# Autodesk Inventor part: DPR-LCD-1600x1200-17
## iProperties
Created: 2004-11
Part Number: DPR-LCD-1600x1200-17
Cost Center: 0 lbmass
Document SubType Name: Modeling
Designer: busseym
Manufacturer: Standard
Standards Organization: Custom
Description: LCD MONITOR, 1600X1200
Stock Number: DPR-LCD-1600x1200-17
Density: 1 g/cm^3
Dept. ID: Product Design
Description #2: ---
Finish #1: ---
Finish #2: ---
Material ID: ---
Project Number: ---
Author: busseym
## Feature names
1. Extrusion1
2. Extrusion2
3. Extrusion3
4. Revolution1
5. Extrusion4
6. Hole1
7. Rectangular Pattern1
8. Extrusion5
9. Extrusion6
10. Extrusion7
11. Extrusion8
12. Extrusion9
13. Extrusion10
14. Extrusion11
15. Hole3
16. Extrusion12
17. Hole4
18. USB BPort [Extrusion]
